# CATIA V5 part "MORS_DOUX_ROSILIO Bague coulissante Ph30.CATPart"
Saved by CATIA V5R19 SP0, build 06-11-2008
Part number: MORS
Bounding box of the stored display mesh (mm): x 0 to 80, y -20 to 20, z 0 to 50
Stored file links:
  C:\Users\Laurent\Desktop\Sujet National E33\CFAO Catia\MORS_DOUX_ROSILIO Bague coulissante Ph30.CATPart
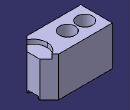
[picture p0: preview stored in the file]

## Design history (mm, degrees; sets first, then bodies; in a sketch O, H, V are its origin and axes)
Body1 (main body)
  Sketch1 on xy-plane, origin (0, 0, 0), H (1, 0, 0), V (0, 1, 0)
    line L1 (80, -20) -> (80, 20)
    line L2 (80, 20) -> (0, 20)
    line L3 (0, 20) -> (0, -20)
    line L4 (0, -20) -> (80, -20)
    distance L2 H = 20
    length L1 = 40
    distance L1 L3 = 80
    horizontal: L2 H, L4 H
    vertical: L1 V, L3 V
  Pad1: profile Sketch1, direction (0, 0, 1), length 50
  Chamfer1: length 12, angle 45, on edge [face of Pad1 from Sketch1.L1 | face of Pad1 from Sketch1.L4]; edge [face of Pad1 from Sketch1.L2 | face of Pad1 from Sketch1.L1]
  Sketch2 on end face of Pad1, origin (0, 0, 45), H (1, 0, 0), V (0, 1, 0)
    circle A1 centre (90, 0) radius 60
    point P1 (90, 0)
    circle A2 centre (90, 0) radius 100.0798
    distance P1 V = 90
    radius A1 = 60
    coincidence: P1 H
  Pocket1: profile Sketch2, direction (0, 0, -1), length 20, deactivated
  Sketch3 on end face of Pad1, origin (0, 0, 45), H (1, 0, 0), V (0, 1, 0)
    circle A1 centre (90, 0) radius 35
    point P1 (90, 0)
    circle A2 centre (90, 0) radius 67.1404
    radius A1 = 35
    distance P1 V = 90
    coincidence: P1 H
  Pocket2: profile Sketch3, direction (0, 0, -1), length 10, deactivated
  Sketch4 on end face of Pad1, origin (59, 0, 45), H (1, 0, 0), V (0, 1, 0)
    point P1 (0, 0)
    reference projected point E1 (0, 0) from Sketch9.P1
    coincidence: E1 P1
  Hole1: placed by Sketch4, at (59, 0, 45) direction (0, 0, -1), diameter 10, through (limit type 3), counterbore diameter 20, counterbore depth 30, deactivated
  Sketch5 on end face of Pad1, origin (37, 0, 50), H (1, 0, 0), V (0, 1, 0)
    point P1 (0, 0)
    reference projected point E1 (0, 0) from Sketch9.P2
    coincidence: E1 P1
  Hole2: placed by Sketch5, at (37, 0, 50) direction (0, 0, -1), diameter 10, through (limit type 3), counterbore diameter 20, counterbore depth 30
  Sketch6 on end face of Pad1, origin (15, 0, 50), H (1, 0, 0), V (0, 1, 0)
    point P1 (0, 0)
    reference projected point E1 (0, 0) from Sketch9.P3
    coincidence: E1 P1
  Hole3: placed by Sketch6, at (15, 0, 50) direction (0, 0, -1), diameter 10, through (limit type 3), counterbore diameter 20, counterbore depth 30
  Sketch7 on start face of Pad1, origin (0, 0, 0), H (1, 0, 0), V (0, -1, 0)
    line L1 (-10.0018, 6.5) -> (90.782, 6.5)
    line L2 (90.782, 6.5) -> (90.782, -6.5)
    line L3 (90.782, -6.5) -> (-10.0018, -6.5)
    line L4 (-10.0018, -6.5) -> (-10.0018, 6.5)
    distance L1 H = 6.5
    length L4 = 13
    horizontal: L1 H, L3 H
    vertical: L2 V, L4 V
  Pocket3: profile Sketch7, direction (0, 0, 1), length 3
  Sketch8 on end face of Pad1, origin (0, 0, 50), H (1, 0, 0), V (0, 1, 0)
    construction line L1 (0, 0) -> (178.7748, 0)
    axis line L2 (80, 50.8156) -> (80, -62.1114)
    circle A1 centre (80, 0) radius 17.45
    point P4 (80, 0)
    distance L2 O = 80
    radius A1 = 17.45
    horizontal: L1 H
    vertical: L2 V
    coincidence: P4 L2, P4 L1
  Pocket4: profile Sketch8, direction (0, 0, -1), length 5.5
  Sketch9 on end face of Pad1, origin (0, 0, 50), H (1, 0, 0), V (0, 1, 0)
    point P1 (59, 0)
    point P2 (37, 0)
    point P3 (15, 0)
    distance P1 P2 = 22
    distance P2 P3 = 22
    distance P3 V = 15
    coincidence: P1 H, P2 H, P3 H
